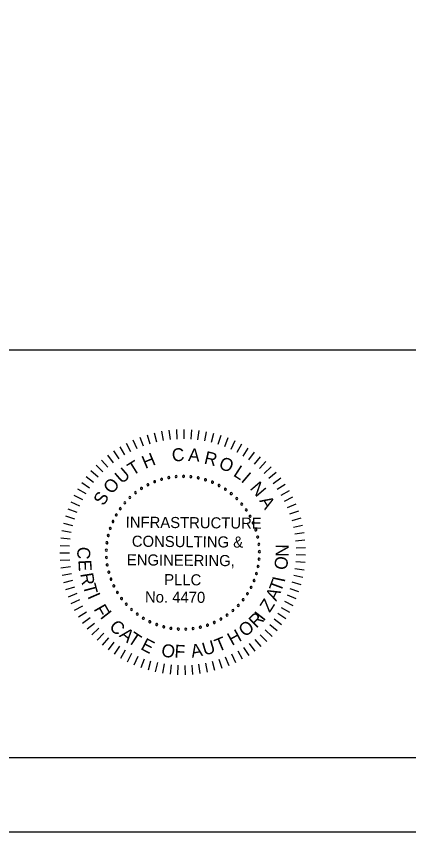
# Model space of a CAD drawing. Extents: x -125.5 to -89.4, y -5.1 to 16.9.
# Drawn here: x -100.32 to -97.68, y -5.07 to 0.43 of the extents above; entities that cross this region are included whole.
import ezdxf

# ---------------------------------------------------------------- set-up
doc = ezdxf.new("R2010")
doc.units = 0
for name, color, linetype in [('BR_BORDER LINES', 7, 'Continuous'), ('BR_TEXT', 7, 'Continuous'), ('Level 31', 7, 'Continuous')]:
    doc.layers.add(name, color=color, linetype=linetype)

msp = doc.modelspace()

# ---------------------------------------------------------------- linework, layer by layer
at = {"layer": 'BR_BORDER LINES'}
for p, q in [((-102.8989, -1.8161), (-97.5337, -1.8161)), ((-123.6994, -4.5662), (-90.0334, -4.5662))]:
    msp.add_line(p, q, dxfattribs=at)
at = {"layer": 'BR_TEXT'}
for p, q in [((-99.2931, -2.3579), (-99.2858, -2.4212)), ((-99.2427, -2.3538), (-99.2394, -2.4174)), ((-99.1923, -2.3527), (-99.1928, -2.4164)), ((-99.1418, -2.3548), (-99.1462, -2.4183)), ((-99.0916, -2.3599), (-99.0999, -2.423)), ((-99.489, -2.4048), (-99.4667, -2.4644)), ((-99.4412, -2.3886), (-99.4226, -2.4495)), ((-99.3925, -2.3754), (-99.3776, -2.4373)), ((-99.343, -2.3651), (-99.332, -2.4278)), ((-99.0418, -2.368), (-99.0539, -2.4305)), ((-98.9925, -2.3792), (-99.0084, -2.4408)), ((-98.9441, -2.3933), (-98.9637, -2.4539)), ((-98.8966, -2.4104), (-98.9199, -2.4696)), ((-99.6253, -2.4703), (-99.5926, -2.5249)), ((-99.5813, -2.4457), (-99.5519, -2.5022)), ((-99.5358, -2.4238), (-99.5099, -2.482)), ((-98.8502, -2.4303), (-98.877, -2.488)), ((-98.8051, -2.453), (-98.8354, -2.509)), ((-99.7086, -2.5273), (-99.6694, -2.5775)), ((-99.6678, -2.4975), (-99.6318, -2.55)), ((-98.7615, -2.4785), (-98.7952, -2.5325)), ((-98.7195, -2.5065), (-98.7564, -2.5584)), ((-99.7475, -2.5595), (-99.7053, -2.6072)), ((-98.6793, -2.5371), (-98.7193, -2.5866)), ((-98.6411, -2.57), (-98.684, -2.617)), ((-99.819, -2.6308), (-99.7713, -2.673)), ((-99.7843, -2.5941), (-99.7393, -2.6391)), ((-98.6049, -2.6052), (-98.6506, -2.6495)), ((-99.8513, -2.6695), (-99.8012, -2.7087)), ((-98.571, -2.6426), (-98.6193, -2.684)), ((-98.5393, -2.6819), (-98.5901, -2.7204)), ((-99.8813, -2.7102), (-99.8288, -2.7463)), ((-98.5102, -2.7232), (-98.5632, -2.7584)), ((-99.9334, -2.7965), (-99.877, -2.826)), ((-99.9087, -2.7526), (-99.8541, -2.7854)), ((-98.4836, -2.7661), (-98.5387, -2.798)), ((-99.9555, -2.842), (-99.8973, -2.8679)), ((-98.4597, -2.8105), (-98.5166, -2.839)), ((-98.4385, -2.8563), (-98.497, -2.8813)), ((-99.9747, -2.8886), (-99.9151, -2.911)), ((-98.4202, -2.9034), (-98.4801, -2.9248)), ((-99.991, -2.9364), (-99.9302, -2.9551)), ((-98.4047, -2.9514), (-98.4659, -2.9691)), ((-100.0044, -2.9851), (-99.9426, -3)), ((-98.3922, -3.0004), (-98.4544, -3.0143)), ((-100.0149, -3.0345), (-99.9522, -3.0456)), ((-98.3828, -3.05), (-98.4456, -3.0601)), ((-100.0266, -3.1347), (-99.963, -3.1382)), ((-100.0222, -3.0844), (-99.959, -3.0917)), ((-98.3763, -3.1), (-98.4397, -3.1063)), ((-100.0278, -3.1852), (-99.9641, -3.1847)), ((-98.373, -3.1504), (-98.4366, -3.1528)), ((-100.026, -3.2356), (-99.9625, -3.2313)), ((-98.3727, -3.2009), (-98.4363, -3.1994)), ((-100.0211, -3.2859), (-99.9579, -3.2777)), ((-98.3813, -3.3014), (-98.4443, -3.2922)), ((-98.3755, -3.2513), (-98.4389, -3.2459)), ((-100.0131, -3.3357), (-99.9506, -3.3237)), ((-98.3902, -3.3511), (-98.4525, -3.3381)), ((-100.0021, -3.385), (-99.9405, -3.3692)), ((-98.4021, -3.4002), (-98.4635, -3.3834)), ((-99.9882, -3.4335), (-99.9276, -3.414)), ((-99.9713, -3.4811), (-99.912, -3.4579)), ((-98.417, -3.4484), (-98.4773, -3.4279)), ((-99.9515, -3.5276), (-99.8937, -3.5008)), ((-98.4554, -3.5417), (-98.5128, -3.514)), ((-98.4348, -3.4957), (-98.4937, -3.4715)), ((-99.929, -3.5727), (-99.8729, -3.5425)), ((-98.4789, -3.5865), (-98.5344, -3.5553)), ((-99.9037, -3.6164), (-99.8496, -3.5828)), ((-99.8758, -3.6585), (-99.8239, -3.6217)), ((-98.505, -3.6297), (-98.5585, -3.5952)), ((-99.8454, -3.6988), (-99.7958, -3.6589)), ((-98.5648, -3.7109), (-98.6137, -3.6702)), ((-98.5336, -3.6712), (-98.5849, -3.6335)), ((-99.8126, -3.7372), (-99.7655, -3.6943)), ((-99.7775, -3.7735), (-99.7331, -3.7278)), ((-98.6341, -3.7843), (-98.6777, -3.7379)), ((-98.5983, -3.7487), (-98.6447, -3.705)), ((-99.7403, -3.8076), (-99.6988, -3.7593)), ((-99.701, -3.8393), (-99.6626, -3.7886)), ((-98.672, -3.8177), (-98.7126, -3.7687)), ((-99.6599, -3.8687), (-99.6246, -3.8157)), ((-99.6171, -3.8954), (-99.5851, -3.8404)), ((-98.7967, -3.9032), (-98.8278, -3.8476)), ((-98.7534, -3.8772), (-98.7879, -3.8237)), ((-98.7118, -3.8487), (-98.7494, -3.7974)), ((-99.5728, -3.9195), (-99.5442, -3.8626)), ((-99.527, -3.9408), (-99.5019, -3.8823)), ((-99.48, -3.9594), (-99.4586, -3.8994)), ((-98.935, -3.9645), (-98.9555, -3.9042)), ((-98.8877, -3.9469), (-98.9118, -3.888)), ((-98.8416, -3.9264), (-98.8692, -3.8691)), ((-99.432, -3.975), (-99.4143, -3.9138)), ((-99.3832, -3.9876), (-99.3692, -3.9255)), ((-99.3336, -3.9973), (-99.3234, -3.9344)), ((-99.2836, -4.0039), (-99.2772, -3.9406)), ((-99.2332, -4.0075), (-99.2307, -3.9438)), ((-99.1827, -4.0079), (-99.1841, -3.9443)), ((-99.1323, -4.0053), (-99.1376, -3.9419)), ((-99.0821, -3.9997), (-99.0913, -3.9367)), ((-99.0324, -3.991), (-99.0454, -3.9286)), ((-98.9833, -3.9792), (-99.0001, -3.9178))]:
    msp.add_line(p, q, dxfattribs=at)
for centre, start, end in [((-99.3424, -2.6889), 16.1422, 196.1422), ((-99.3424, -2.6889), 196.1422, 16.1422), ((-99.2939, -2.6775), 10.6038, 190.6038), ((-99.2939, -2.6775), 190.6038, 10.6038), ((-99.2445, -2.6708), 5.0653, 185.0653), ((-99.2445, -2.6708), 185.0653, 5.0653), ((-99.1947, -2.6689), 359.5268, 179.5268), ((-99.1947, -2.6689), 179.5268, 359.5268), ((-99.145, -2.6718), 173.9884, 353.9884), ((-99.145, -2.6718), 353.9884, 173.9884), ((-99.0957, -2.6795), 168.4499, 348.4499), ((-99.0957, -2.6795), 348.4499, 168.4499), ((-99.0475, -2.6919), 162.9114, 342.9114), ((-99.0475, -2.6919), 342.9114, 162.9114), ((-99.4782, -2.7503), 32.7576, 212.7576), ((-99.4782, -2.7503), 212.7576, 32.7576), ((-99.435, -2.7255), 27.2191, 207.2191), ((-99.435, -2.7255), 207.2191, 27.2191), ((-99.3896, -2.705), 21.6807, 201.6807), ((-99.3896, -2.705), 201.6807, 21.6807), ((-99.0006, -2.709), 157.373, 337.373), ((-99.0006, -2.709), 337.373, 157.373), ((-98.9557, -2.7304), 151.8345, 331.8345), ((-98.9557, -2.7304), 331.8345, 151.8345), ((-98.913, -2.7561), 326.2961, 146.2961), ((-99.5564, -2.8119), 43.8345, 223.8345), ((-99.5188, -2.7792), 38.2961, 218.2961), ((-99.5188, -2.7792), 218.2961, 38.2961), ((-98.913, -2.7561), 146.2961, 326.2961), ((-98.873, -2.7858), 140.7576, 320.7576), ((-98.873, -2.7858), 320.7576, 140.7576), ((-99.5907, -2.848), 49.373, 229.373), ((-99.5907, -2.848), 229.373, 49.373), ((-99.5564, -2.8119), 223.8345, 43.8345), ((-98.836, -2.8192), 135.2191, 315.2191), ((-98.836, -2.8192), 315.2191, 135.2191), ((-98.8024, -2.8561), 129.6807, 309.6807), ((-98.8024, -2.8561), 309.6807, 129.6807), ((-99.6214, -2.8873), 54.9114, 234.9114), ((-99.6214, -2.8873), 234.9114, 54.9114), ((-98.7726, -2.896), 124.1422, 304.1422), ((-98.7726, -2.896), 304.1422, 124.1422), ((-99.6706, -2.9738), 65.9884, 245.9884), ((-99.6706, -2.9738), 245.9884, 65.9884), ((-99.6481, -2.9293), 60.4499, 240.4499), ((-99.6481, -2.9293), 240.4499, 60.4499), ((-98.7467, -2.9386), 118.6038, 298.6038), ((-98.7467, -2.9386), 298.6038, 118.6038), ((-99.6888, -3.0202), 71.5268, 251.5268), ((-99.6888, -3.0202), 251.5268, 71.5268), ((-98.7251, -2.9835), 113.0653, 293.0653), ((-98.7251, -2.9835), 293.0653, 113.0653), ((-98.7079, -3.0302), 107.5268, 287.5268), ((-98.7079, -3.0302), 287.5268, 107.5268), ((-99.7024, -3.0681), 77.0653, 257.0653), ((-99.7024, -3.0681), 257.0653, 77.0653), ((-98.6953, -3.0785), 101.9884, 281.9884), ((-98.6953, -3.0785), 281.9884, 101.9884), ((-99.7113, -3.1172), 82.6038, 262.6038), ((-99.7113, -3.1172), 262.6038, 82.6038), ((-98.6874, -3.1277), 96.4499, 276.4499), ((-98.6874, -3.1277), 276.4499, 96.4499), ((-99.7154, -3.1668), 88.1422, 268.1422), ((-99.7154, -3.1668), 268.1422, 88.1422), ((-98.6843, -3.1774), 90.9114, 270.9114), ((-98.6843, -3.1774), 270.9114, 90.9114), ((-99.7147, -3.2167), 93.6807, 273.6807), ((-99.7147, -3.2167), 273.6807, 93.6807), ((-98.686, -3.2272), 85.373, 265.373), ((-98.686, -3.2272), 265.373, 85.373), ((-99.7092, -3.2662), 99.2191, 279.2191), ((-99.7092, -3.2662), 279.2191, 99.2191), ((-98.6926, -3.2766), 79.8345, 259.8345), ((-98.6926, -3.2766), 259.8345, 79.8345), ((-99.6989, -3.3149), 104.7576, 284.7576), ((-99.6989, -3.3149), 284.7576, 104.7576), ((-98.7038, -3.3251), 74.2961, 254.2961), ((-98.7038, -3.3251), 254.2961, 74.2961), ((-99.684, -3.3625), 110.2961, 290.2961), ((-99.684, -3.3625), 290.2961, 110.2961), ((-99.6646, -3.4084), 115.8345, 295.8345), ((-99.6646, -3.4084), 295.8345, 115.8345), ((-98.7197, -3.3724), 68.7576, 248.7576), ((-98.7197, -3.3724), 248.7576, 68.7576), ((-99.6408, -3.4522), 121.373, 301.373), ((-99.6408, -3.4522), 301.373, 121.373), ((-98.7647, -3.4611), 57.6807, 237.6807), ((-98.7647, -3.4611), 237.6807, 57.6807), ((-98.7401, -3.4178), 63.2191, 243.2191), ((-98.7401, -3.4178), 243.2191, 63.2191), ((-99.6129, -3.4935), 126.9114, 306.9114), ((-99.6129, -3.4935), 306.9114, 126.9114), ((-98.7934, -3.5019), 52.1422, 232.1422), ((-98.7934, -3.5019), 232.1422, 52.1422), ((-99.5812, -3.5319), 132.4499, 312.4499), ((-99.5812, -3.5319), 312.4499, 132.4499), ((-99.5459, -3.5671), 137.9884, 317.9884), ((-99.5459, -3.5671), 317.9884, 137.9884), ((-98.862, -3.5741), 41.0653, 221.0653), ((-98.862, -3.5741), 221.0653, 41.0653), ((-98.826, -3.5396), 46.6038, 226.6038), ((-98.826, -3.5396), 226.6038, 46.6038), ((-99.5074, -3.5987), 143.5268, 323.5268), ((-99.5074, -3.5987), 323.5268, 143.5268), ((-99.466, -3.6264), 149.0653, 329.0653), ((-99.466, -3.6264), 329.0653, 149.0653), ((-98.9431, -3.6317), 29.9884, 209.9884), ((-98.9431, -3.6317), 209.9884, 29.9884), ((-98.9012, -3.6049), 35.5268, 215.5268), ((-98.9012, -3.6049), 215.5268, 35.5268), ((-99.4221, -3.65), 154.6038, 334.6038), ((-99.4221, -3.65), 334.6038, 154.6038), ((-99.3761, -3.6693), 160.1422, 340.1422), ((-99.3761, -3.6693), 340.1422, 160.1422), ((-99.3285, -3.684), 165.6807, 345.6807), ((-99.3285, -3.684), 345.6807, 165.6807), ((-99.0817, -3.6865), 13.373, 193.373), ((-99.0817, -3.6865), 193.373, 13.373), ((-99.0338, -3.6728), 18.9114, 198.9114), ((-99.0338, -3.6728), 198.9114, 18.9114), ((-98.9875, -3.6545), 24.4499, 204.4499), ((-98.9875, -3.6545), 204.4499, 24.4499), ((-99.2797, -3.6941), 351.2191, 171.2191), ((-99.2797, -3.6941), 171.2191, 351.2191), ((-99.2302, -3.6994), 356.7576, 176.7576), ((-99.2302, -3.6994), 176.7576, 356.7576), ((-99.1803, -3.6999), 2.2961, 182.2961), ((-99.1803, -3.6999), 182.2961, 2.2961), ((-99.1307, -3.6956), 7.8345, 187.8345), ((-99.1307, -3.6956), 187.8345, 7.8345)]:
    msp.add_arc(centre, 0.00701, start, end, dxfattribs=at)
at = {"layer": 'Level 31'}
msp.add_lwpolyline([(-125.5328, 16.9339), (-125.5328, -5.0661), (-89.5328, -5.0661), (-89.5328, 16.9339)], dxfattribs=at)

# ---------------------------------------------------------------- texts
at = {"layer": 'BR_TEXT'}
for s, height, rotation, p in [('H', 0.0872, 22.7882, (-99.453, -2.6197)), ('C', 0.0872, 4.7281, (-99.2702, -2.5703)), ('A', 0.0872, 355.6981, (-99.1657, -2.5654)), ('R', 0.0872, 346.6681, (-99.0615, -2.5824)), ('T', 0.0872, 31.8182, (-99.5379, -2.6674)), ('O', 0.0872, 337.638, (-98.9637, -2.6122)), ('U', 0.0872, 40.8482, (-99.6112, -2.7235)), ('L', 0.0872, 327.108, (-98.8649, -2.6626)), ('O', 0.0872, 49.8782, (-99.6782, -2.7945)), ('I', 0.0872, 319.578, (-98.8123, -2.7005)), ('N', 0.0872, 310.548, (-98.7515, -2.7512)), ('S', 0.0872, 58.9083, (-99.7336, -2.8727)), ('A', 0.0872, 301.5179, (-98.6864, -2.8336)), ('INFRASTRUCTURE', 0.074771, 359.5268, (-99.585, -3.0152)), ('CONSULTING &', 0.074771, 359.5268, (-99.5437, -3.1438)), ('C', 0.0872, 267.025, (-99.9086, -3.1426)), ('N', 0.0872, 89.2085, (-98.4872, -3.2124)), ('E', 0.0872, 273.025, (-99.9042, -3.2342)), ('ENGINEERING,', 0.074771, 359.5268, (-99.5773, -3.2693)), ('O', 0.0872, 83.2085, (-98.4982, -3.3038)), ('R', 0.0872, 279.025, (-99.8914, -3.3265)), ('PLLC', 0.07477, 359.5268, (-99.3256, -3.4028)), ('I', 0.0872, 77.9093, (-98.5137, -3.3881)), ('T', 0.0872, 285.025, (-99.874, -3.4053)), ('T', 0.0872, 69.3954, (-98.5394, -3.4556)), ('I', 0.0872, 293.7713, (-99.8443, -3.4784)), ('No. 4470', 0.07477, 359.5268, (-99.4551, -3.5197)), ('A', 0.0872, 63.3954, (-98.5702, -3.516)), ('Z', 0.0872, 57.3954, (-98.6141, -3.5923)), ('F', 0.0872, 299.7713, (-99.8031, -3.5644)), ('I', 0.0872, 308.5268, (-99.761, -3.6183)), ('R', 0.0872, 44.5268, (-98.7045, -3.6973)), ('I', 0.0872, 52.3339, (-98.6551, -3.65)), ('C', 0.0872, 314.5268, (-99.7017, -3.6884)), ('O', 0.0872, 38.5268, (-98.7811, -3.7572)), ('A', 0.0872, 320.5268, (-99.6325, -3.747)), ('T', 0.0872, 326.5268, (-99.5781, -3.7855)), ('H', 0.0872, 28.5268, (-98.8692, -3.8132)), ('E', 0.0872, 332.5268, (-99.4895, -3.8332)), ('U', 0.0872, 16.5268, (-99.0541, -3.8794)), ('T', 0.0872, 22.5268, (-98.9624, -3.855)), ('O', 0.0872, 350.5268, (-99.3494, -3.8821)), ('F', 0.0872, 356.5268, (-99.2579, -3.8912)), ('A', 0.0872, 10.5268, (-99.138, -3.8929))]:
    msp.add_text(s, height=height, rotation=rotation, dxfattribs=at).set_placement(p)

doc.saveas('drawing.dxf')
